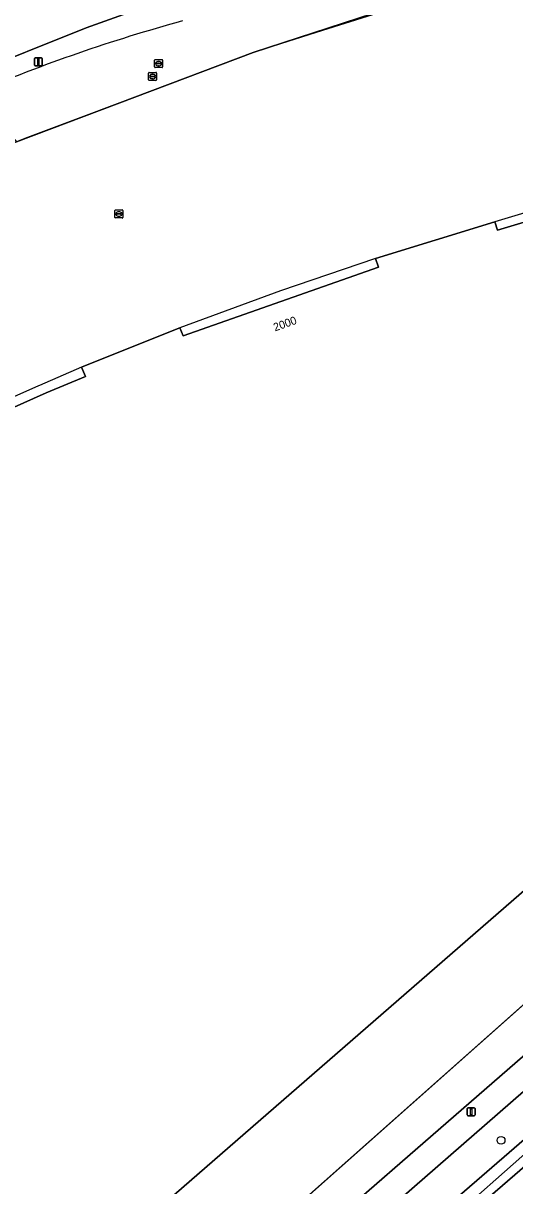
# Model space of a CAD drawing. Extents: x 155018 to 156648, y 383979 to 385733.
# Drawn here: x 155861.9 to 155923.3, y 384081.4 to 384226.6 of the extents above; entities that cross this region are included whole.
import ezdxf

# ---------------------------------------------------------------- set-up
doc = ezdxf.new("R2010")
doc.units = 0
for name, color, linetype in [('IMGEO_Berm_groen', 7, 'Continuous'), ('IMGEO_Boom', 7, 'Continuous'), ('IMGEO_Brandkraan', 7, 'Continuous'), ('IMGEO_Erf', 7, 'Continuous'), ('IMGEO_Groenvoorziening', 7, 'Continuous'), ('IMGEO_Lichtmast', 7, 'Continuous'), ('IMGEO_Lijnafwatering', 7, 'Continuous'), ('IMGEO_Loofbos', 7, 'Continuous'), ('IMGEO_Oever', 7, 'Continuous'), ('IMGEO_Pand', 7, 'Continuous'), ('IMGEO_Pand_nummerreeks', 7, 'Continuous'), ('IMGEO_Pand_overbouw', 7, 'Continuous'), ('IMGEO_Rijbaan_lokaal_gesloten', 7, 'Continuous'), ('IMGEO_Rijbaan_regionaal_gesloten', 7, 'Continuous'), ('IMGEO_Rioolput', 7, 'Continuous'), ('IMGEO_Waterloop', 7, 'Continuous')]:
    doc.layers.add(name, color=color, linetype=linetype)

msp = doc.modelspace()

# ---------------------------------------------------------------- linework, layer by layer
at = {"layer": 'IMGEO_Berm_groen'}
msp.add_lwpolyline([(155964.65, 384260.75), (155910.96, 384240.78), (155869.79, 384226.04), (155854.81, 384220.04), (155838.88, 384213.66), (155817.99, 384203.11), (155797.79, 384190.44), (155774.33, 384174.73), (155772.78, 384174.58), (155771.15, 384174.42)], dxfattribs=at)
msp.add_arc((155936.01, 384028.77), 205.4, 105.2921, 112.9402, dxfattribs=at)
at = {"layer": 'IMGEO_Boom'}
msp.add_circle((155921.62, 384087.09), 0.489, dxfattribs=at)
at = {"layer": 'IMGEO_Brandkraan'}
for p, q in [((155873.38, 384202.36), (155873.38, 384203.22)), ((155873.45, 384203.29), (155874.3, 384203.29)), ((155873.63, 384202.78), (155873.63, 384202.8)), ((155874.07, 384202.75), (155873.67, 384202.75)), ((155873.68, 384202.83), (155874.08, 384202.83)), ((155873.86, 384203.07), (155873.89, 384203.07)), ((155874.12, 384202.8), (155874.12, 384202.78)), ((155874.38, 384203.22), (155874.38, 384202.36)), ((155874.3, 384202.29), (155873.45, 384202.29)), ((155873.89, 384202.51), (155873.86, 384202.51))]:
    msp.add_line(p, q, dxfattribs=at)
for points in [[(155873.38, 384202.36), (155873.38, 384203.22)], [(155873.45, 384203.29), (155874.3, 384203.29)], [(155874.38, 384203.22), (155874.38, 384202.36)], [(155874.3, 384202.29), (155873.45, 384202.29)]]:
    msp.add_lwpolyline(points, dxfattribs=at)
for centre, radius, start, end in [((155873.45, 384203.21), 0.0765, 91.552, 178.448), ((155873.45, 384203.21), 0.0765, 91.552, 178.448), ((155873.68, 384202.79), 0.0403, 85.8775, 175.7526), ((155873.67, 384202.78), 0.0366, 178.938, 274.7102), ((155874.08, 384202.79), 0.043, 264.8664, 352.4533), ((155874.08, 384202.79), 0.0386, 1.7309, 96.639), ((155874.3, 384203.21), 0.0765, 1.552, 88.448), ((155874.3, 384203.21), 0.0765, 1.552, 88.448), ((155873.45, 384202.36), 0.0765, 181.552, 268.448), ((155873.45, 384202.36), 0.0765, 181.552, 268.448), ((155874.3, 384202.36), 0.0765, 271.552, 358.448), ((155874.3, 384202.36), 0.0765, 271.552, 358.448)]:
    msp.add_arc(centre, radius, start, end, dxfattribs=at)
for centre, major_axis, ratio, start_param, end_param in [((155873.86, 384202.79), (-0.387, 0.002), 0.722429, 4.712389, 7.853982), ((155873.89, 384202.79), (-0.39, 0.002), 0.717154, 1.570796, 4.712389)]:
    msp.add_ellipse(centre, major_axis=major_axis, ratio=ratio, start_param=start_param, end_param=end_param, dxfattribs=at)
at = {"layer": 'IMGEO_Erf'}
for points in [[(155979.1, 384247.52), (155974.3, 384246.67), (155972.23, 384246.35), (155971.83, 384246.26), (155961.42, 384243.86), (155928.56, 384235), (155907.5, 384228.44), (155890.67, 384222.94), (155861.08, 384211.82)], [(155850.44, 384174.02), (155864.81, 384180.44), (155869.69, 384182.48), (155869.22, 384183.64), (155881.37, 384188.53), (155881.51, 384188.58), (155881.91, 384187.56), (155906.31, 384196.14), (155905.92, 384197.21), (155920.85, 384201.8), (155921.18, 384200.75), (155936.69, 384205.41)], [(155857.75, 384044.83), (155954.02, 384130.33), (156024.19, 384193.57)], [(155949.7, 384140.19), (155851.33, 384054.72)]]:
    msp.add_lwpolyline(points, dxfattribs=at)
at = {"layer": 'IMGEO_Groenvoorziening'}
for points in [[(155873.51, 384048.82), (156000, 384159.05), (156019.61, 384178.34), (156030.71, 384188.63), (156039.46, 384198.55), (156042.71, 384206.63), (156043.77, 384213.44), (156043.94, 384218.73), (156043.34, 384225.77), (156037.36, 384236.9), (156032.18, 384241.15), (156029.37, 384242.78)], [(155957.51, 384126.41), (155857.5, 384039.48), (155854.07, 384036.74)]]:
    msp.add_lwpolyline(points, dxfattribs=at)
at = {"layer": 'IMGEO_Lichtmast'}
for p, q in [((155863.32, 384221.39), (155863.32, 384222.19)), ((155863.32, 384222.19), (155863.32, 384221.39)), ((155863.42, 384222.29), (155864.21, 384222.29)), ((155864.21, 384222.29), (155863.42, 384222.29)), ((155864.31, 384222.19), (155864.31, 384221.39)), ((155864.31, 384221.39), (155864.31, 384222.19)), ((155864.21, 384221.29), (155863.42, 384221.29)), ((155863.42, 384221.29), (155864.21, 384221.29)), ((155917.38, 384090.25), (155917.38, 384091.05)), ((155917.38, 384091.05), (155917.38, 384090.25)), ((155917.48, 384091.15), (155918.27, 384091.15)), ((155918.27, 384091.15), (155917.48, 384091.15)), ((155918.37, 384091.05), (155918.37, 384090.25)), ((155918.37, 384090.25), (155918.37, 384091.05)), ((155918.27, 384090.15), (155917.48, 384090.15)), ((155917.48, 384090.15), (155918.27, 384090.15))]:
    msp.add_line(p, q, dxfattribs=at)
for points in [[(155863.74, 384222.17), (155863.89, 384222.17), (155863.89, 384221.42), (155863.74, 384221.42), (155863.74, 384222.17)], [(155917.8, 384091.03), (155917.95, 384091.03), (155917.95, 384090.28), (155917.8, 384090.28), (155917.8, 384091.03)]]:
    msp.add_lwpolyline(points, dxfattribs=at)
for centre, start, end in [((155863.42, 384222.19), 90, 180), ((155863.42, 384222.19), 90, 180), ((155864.21, 384222.19), 0, 90), ((155864.21, 384222.19), 360, 90), ((155863.42, 384221.39), 180, 270), ((155863.42, 384221.39), 180, 270), ((155864.21, 384221.39), 270, 0), ((155864.21, 384221.39), 270, 0), ((155917.48, 384091.05), 90, 180), ((155917.48, 384091.05), 90, 180), ((155918.27, 384091.05), 0, 90), ((155918.27, 384091.05), 360, 90), ((155917.48, 384090.25), 180, 270), ((155917.48, 384090.25), 180, 270), ((155918.27, 384090.25), 270, 0), ((155918.27, 384090.25), 270, 0)]:
    msp.add_arc(centre, 0.1, start, end, dxfattribs=at)
at = {"layer": 'IMGEO_Lijnafwatering'}
for points in [[(155918.16, 384231.68), (155899.32, 384225.69)], [(155899.32, 384225.69), (155890.67, 384222.94), (155880.66, 384219.18)], [(155880.66, 384219.18), (155862.15, 384212.22)], [(155862.15, 384212.22), (155861.08, 384211.82), (155844.09, 384204.21)], [(155923.18, 384102.94), (155937.96, 384116.07)], [(155908.4, 384089.81), (155923.18, 384102.94)], [(155893.62, 384076.69), (155908.4, 384089.81)]]:
    msp.add_lwpolyline(points, dxfattribs=at)
at = {"layer": 'IMGEO_Loofbos'}
for points in [[(155774.33, 384174.73), (155797.79, 384190.44), (155817.99, 384203.11), (155838.88, 384213.66), (155854.81, 384220.04), (155869.79, 384226.04), (155910.96, 384240.78), (155964.65, 384260.75)], [(156091.06, 384239.03), (156073.68, 384223.07), (156064.77, 384215.32), (156000, 384159.05), (155873.51, 384048.82)], [(155872.58, 384043.05), (155874.02, 384040.11), (155874.57, 384040.38), (155875.1, 384041.22), (155876.99, 384043.96), (155879.06, 384046.39), (155881.18, 384048.34), (155883.54, 384050.49), (155888.56, 384055.1), (155898.77, 384064.52), (155913.64, 384077.77), (155929.44, 384091.49), (155933.58, 384094.83), (155948.91, 384108.58), (155953.4, 384112.13), (155955.98, 384113.84), (155957.9, 384116.31), (155970.75, 384127.03), (155989.93, 384144.17), (156009.53, 384160.35)]]:
    msp.add_lwpolyline(points, dxfattribs=at)
at = {"layer": 'IMGEO_Oever'}
for points in [[(155880.65, 384046.55), (155933.22, 384093.01), (156034.53, 384180.9), (156084.09, 384223.86)], [(156057.78, 384199.37), (155977.12, 384129.18), (155966.04, 384119.71), (155905.53, 384067.36)], [(156042.41, 384191.17), (156041.49, 384189.74), (156040.52, 384188.21), (156040.32, 384187.98), (156039.34, 384186.85), (156026.93, 384175.88), (156022.22, 384171.62), (156009.53, 384160.35), (155989.93, 384144.17), (155970.75, 384127.03), (155957.9, 384116.31), (155955.98, 384113.84), (155953.4, 384112.13), (155948.91, 384108.58), (155933.58, 384094.83), (155929.44, 384091.49), (155913.64, 384077.77)]]:
    msp.add_lwpolyline(points, dxfattribs=at)
at = {"layer": 'IMGEO_Pand'}
for points in [[(155936.69, 384205.41), (155921.18, 384200.75), (155920.85, 384201.8), (155905.92, 384197.21), (155906.31, 384196.14), (155881.91, 384187.56), (155881.51, 384188.58), (155881.37, 384188.53), (155869.22, 384183.64), (155869.69, 384182.48), (155864.81, 384180.44), (155850.44, 384174.02)], [(155851.33, 384054.72), (155949.7, 384140.19)]]:
    msp.add_lwpolyline(points, dxfattribs=at)
at = {"layer": 'IMGEO_Pand_overbouw'}
for points in [[(155920.85, 384201.8), (155921.18, 384200.75), (155936.69, 384205.41), (155936.37, 384206.46)], [(155881.51, 384188.58), (155881.91, 384187.56), (155906.31, 384196.14), (155905.92, 384197.21), (155894.06, 384193.21)], [(155850.02, 384175.06), (155850.44, 384174.02), (155864.81, 384180.44), (155869.69, 384182.48), (155869.22, 384183.64), (155863.98, 384181.37), (155863.85, 384181.32), (155856.89, 384178.23)]]:
    msp.add_lwpolyline(points, close=True, dxfattribs=at)
at = {"layer": 'IMGEO_Rijbaan_lokaal_gesloten'}
msp.add_lwpolyline([(155854.07, 384036.74), (155857.5, 384039.48), (155957.51, 384126.41), (155954.02, 384130.33), (155857.75, 384044.83)], dxfattribs=at)
at = {"layer": 'IMGEO_Rijbaan_regionaal_gesloten'}
msp.add_lwpolyline([(155855.95, 384217.92), (155861.08, 384211.82), (155890.67, 384222.94), (155907.5, 384228.44), (155928.56, 384235), (155961.42, 384243.86), (155971.83, 384246.26), (155972.23, 384246.35), (155974.3, 384246.67), (155995.63, 384253.41)], dxfattribs=at)
msp.add_arc((155936.01, 384028.77), 205.4, 105.2921, 112.9402, dxfattribs=at)
at = {"layer": 'IMGEO_Rioolput'}
for p, q in [((155878.34, 384221.15), (155878.34, 384222)), ((155878.42, 384222.07), (155879.27, 384222.07)), ((155878.6, 384221.57), (155878.6, 384221.58)), ((155878.64, 384221.62), (155879.04, 384221.62)), ((155879.04, 384221.53), (155878.64, 384221.53)), ((155878.83, 384221.85), (155878.85, 384221.85)), ((155879.08, 384221.58), (155879.08, 384221.57)), ((155879.34, 384222), (155879.34, 384221.15)), ((155877.59, 384219.54), (155877.59, 384220.39)), ((155877.66, 384220.46), (155878.52, 384220.46)), ((155878.08, 384220.24), (155878.1, 384220.24)), ((155879.27, 384221.07), (155878.42, 384221.07)), ((155878.59, 384220.39), (155878.59, 384219.54)), ((155878.85, 384221.29), (155878.83, 384221.29)), ((155878.52, 384219.46), (155877.66, 384219.46)), ((155877.85, 384219.96), (155877.85, 384219.97)), ((155877.89, 384220.01), (155878.29, 384220.01)), ((155878.29, 384219.92), (155877.89, 384219.92)), ((155878.1, 384219.68), (155878.08, 384219.68)), ((155878.33, 384219.97), (155878.33, 384219.96))]:
    msp.add_line(p, q, dxfattribs=at)
for points in [[(155878.34, 384221.15), (155878.34, 384222)], [(155878.42, 384222.07), (155879.27, 384222.07)], [(155879.34, 384222), (155879.34, 384221.15)], [(155877.59, 384219.54), (155877.59, 384220.39)], [(155877.66, 384220.46), (155878.52, 384220.46)], [(155879.27, 384221.07), (155878.42, 384221.07)], [(155878.59, 384220.39), (155878.59, 384219.54)], [(155878.52, 384219.46), (155877.66, 384219.46)]]:
    msp.add_lwpolyline(points, dxfattribs=at)
for centre, radius, start, end in [((155878.42, 384222), 0.0765, 91.552, 178.448), ((155878.42, 384222), 0.0765, 91.552, 178.448), ((155878.64, 384221.58), 0.0403, 85.8775, 175.7526), ((155878.64, 384221.57), 0.0366, 178.938, 274.7102), ((155879.05, 384221.58), 0.0386, 1.7309, 96.639), ((155879.04, 384221.57), 0.043, 264.8664, 352.4533), ((155879.27, 384222), 0.0765, 1.552, 88.448), ((155879.27, 384222), 0.0765, 1.552, 88.448), ((155877.67, 384220.39), 0.0765, 91.552, 178.448), ((155877.67, 384220.39), 0.0765, 91.552, 178.448), ((155878.42, 384221.15), 0.0765, 181.552, 268.448), ((155878.42, 384221.15), 0.0765, 181.552, 268.448), ((155878.51, 384220.39), 0.0765, 1.552, 88.448), ((155878.51, 384220.39), 0.0765, 1.552, 88.448), ((155879.27, 384221.15), 0.0765, 271.552, 358.448), ((155879.27, 384221.15), 0.0765, 271.552, 358.448), ((155877.67, 384219.54), 0.0765, 181.552, 268.448), ((155877.67, 384219.54), 0.0765, 181.552, 268.448), ((155877.89, 384219.97), 0.0403, 85.8775, 175.7526), ((155877.89, 384219.96), 0.0366, 178.938, 274.7102), ((155878.29, 384219.97), 0.0386, 1.7309, 96.639), ((155878.29, 384219.96), 0.043, 264.8664, 352.4533), ((155878.51, 384219.54), 0.0765, 271.552, 358.448), ((155878.51, 384219.54), 0.0765, 271.552, 358.448)]:
    msp.add_arc(centre, radius, start, end, dxfattribs=at)
for centre, major_axis, ratio, start_param, end_param in [((155878.83, 384221.57), (-0.387, 0.002), 0.722429, 4.712389, 7.853982), ((155878.85, 384221.57), (-0.39, 0.002), 0.717154, 1.570796, 4.712389), ((155878.08, 384219.96), (-0.387, 0.002), 0.722429, 4.712389, 7.853982), ((155878.1, 384219.96), (-0.39, 0.002), 0.717154, 1.570796, 4.712389)]:
    msp.add_ellipse(centre, major_axis=major_axis, ratio=ratio, start_param=start_param, end_param=end_param, dxfattribs=at)
at = {"layer": 'IMGEO_Waterloop'}
for points in [[(156084.09, 384223.86), (156034.53, 384180.9), (155933.22, 384093.01), (155880.65, 384046.55)], [(155905.53, 384067.36), (155966.04, 384119.71), (155977.12, 384129.18), (156057.78, 384199.37)]]:
    msp.add_lwpolyline(points, dxfattribs=at)

# ---------------------------------------------------------------- texts
at = {"layer": 'IMGEO_Pand_nummerreeks'}
msp.add_text('2000', height=1, rotation=19.3856, dxfattribs=at).set_placement((155893.38, 384188.12))

doc.saveas('drawing.dxf')
